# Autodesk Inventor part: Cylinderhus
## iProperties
Created: 2007-04
Part Number: Cylinderhus
Document SubType Name: Modeling
Designer: kurs1
Density: 1 g/cm^3
Author: kurs1
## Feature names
1. Extrusion1
2. Extrusion2
3. Extrusion3
4. Extrusion4
5. Extrusion5
6. Extrusion6
7. Hole1
8. Extrusion7
